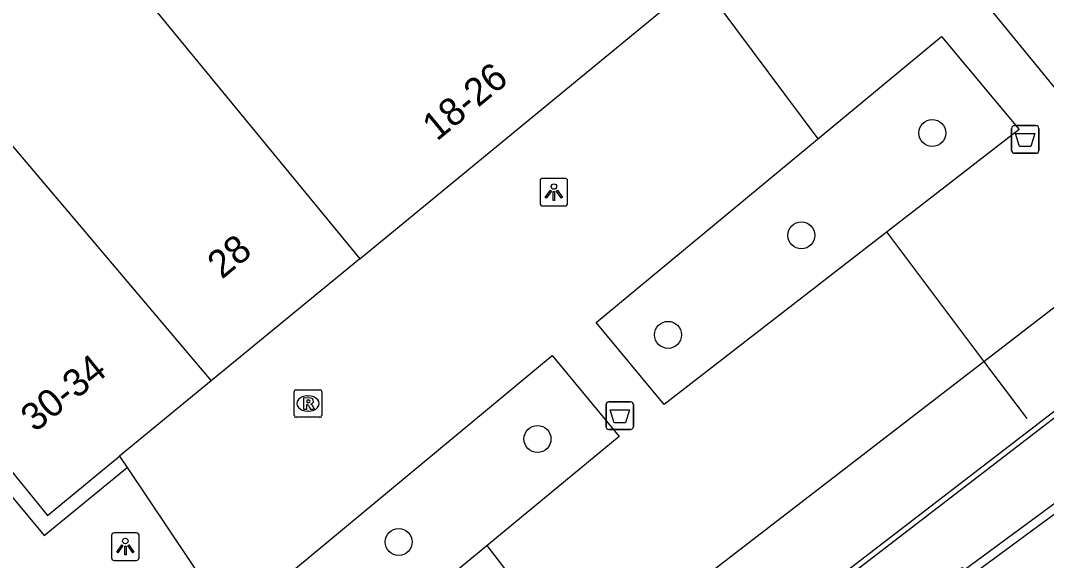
# Model space of a CAD drawing. Extents: x 161087 to 161922, y 382574 to 383873.
# Drawn here: x 161349.71 to 161386.87, y 383109.41 to 383128.96 of the extents above; entities that cross this region are included whole.
import ezdxf

# ---------------------------------------------------------------- set-up
doc = ezdxf.new("R2010")
doc.units = 0
for name, color, linetype in [('IMGEO_Afvalbak', 7, 'Continuous'), ('IMGEO_Boom', 7, 'Continuous'), ('IMGEO_Lichtpunt', 7, 'Continuous'), ('IMGEO_Lijnafwatering', 7, 'Continuous'), ('IMGEO_Muur', 7, 'Continuous'), ('IMGEO_Pand', 7, 'Continuous'), ('IMGEO_Pand_nummerreeks', 7, 'Continuous'), ('IMGEO_Rioolput', 7, 'Continuous'), ('IMGEO_Voetgangersgebied_open', 7, 'Continuous')]:
    doc.layers.add(name, color=color, linetype=linetype)

msp = doc.modelspace()

# ---------------------------------------------------------------- linework, layer by layer
at = {"layer": 'IMGEO_Afvalbak'}
for p, q in [((161385.607, 383124.25), (161385.607, 383125.05)), ((161385.607, 383125.05), (161385.607, 383124.25)), ((161385.707, 383125.15), (161386.497, 383125.15)), ((161386.497, 383125.15), (161385.707, 383125.15)), ((161386.597, 383125.05), (161386.597, 383124.25)), ((161386.597, 383124.25), (161386.597, 383125.05)), ((161386.497, 383124.15), (161385.707, 383124.15)), ((161385.707, 383124.15), (161386.497, 383124.15)), ((161370.919, 383114.252), (161370.919, 383115.052)), ((161370.919, 383115.052), (161370.919, 383114.252)), ((161371.019, 383115.152), (161371.809, 383115.152)), ((161371.809, 383115.152), (161371.019, 383115.152)), ((161371.909, 383115.052), (161371.909, 383114.252)), ((161371.909, 383114.252), (161371.909, 383115.052)), ((161371.809, 383114.152), (161371.019, 383114.152)), ((161371.019, 383114.152), (161371.809, 383114.152))]:
    msp.add_line(p, q, dxfattribs=at)
for points in [[(161385.75, 383124.864), (161386.454, 383124.864), (161386.305, 383124.394), (161385.899, 383124.394), (161385.75, 383124.864)], [(161371.062, 383114.866), (161371.766, 383114.866), (161371.617, 383114.396), (161371.211, 383114.396), (161371.062, 383114.866)]]:
    msp.add_lwpolyline(points, dxfattribs=at)
for centre, start, end in [((161385.707, 383125.05), 90, 180), ((161385.707, 383125.05), 90, 180), ((161386.497, 383125.05), 0, 90), ((161386.497, 383125.05), 360, 90), ((161385.707, 383124.25), 180, 270), ((161385.707, 383124.25), 180, 270), ((161386.497, 383124.25), 270, 0), ((161386.497, 383124.25), 270, 0), ((161371.019, 383115.052), 90, 180), ((161371.019, 383115.052), 90, 180), ((161371.809, 383115.052), 0, 90), ((161371.809, 383115.052), 360, 90), ((161371.019, 383114.252), 180, 270), ((161371.019, 383114.252), 180, 270), ((161371.809, 383114.252), 270, 0), ((161371.809, 383114.252), 270, 0)]:
    msp.add_arc(centre, 0.1, start, end, dxfattribs=at)
at = {"layer": 'IMGEO_Boom'}
for centre in [(161382.735, 383124.885), (161377.996, 383121.178), (161373.166, 383117.575), (161368.435, 383113.807), (161363.406, 383110.079)]:
    msp.add_circle(centre, 0.489, dxfattribs=at)
at = {"layer": 'IMGEO_Lichtpunt'}
for p, q in [((161368.53, 383123.147), (161368.53, 383122.34)), ((161368.53, 383123.147), (161368.53, 383122.34)), ((161369.432, 383123.242), (161368.624, 383123.242)), ((161369.432, 383123.242), (161368.624, 383123.242)), ((161369.526, 383122.34), (161369.526, 383123.147)), ((161369.526, 383122.34), (161369.526, 383123.147)), ((161368.624, 383122.246), (161369.432, 383122.246)), ((161368.624, 383122.246), (161369.432, 383122.246)), ((161353.909, 383110.408), (161353.101, 383110.408)), ((161353.909, 383110.408), (161353.101, 383110.408)), ((161353.007, 383110.313), (161353.007, 383109.506)), ((161353.007, 383110.313), (161353.007, 383109.506)), ((161354.003, 383109.506), (161354.003, 383110.313)), ((161354.003, 383109.506), (161354.003, 383110.313)), ((161353.101, 383109.412), (161353.909, 383109.412)), ((161353.101, 383109.412), (161353.909, 383109.412))]:
    msp.add_line(p, q, dxfattribs=at)
for points in [[(161368.904, 383122.811), (161368.943, 383122.783), (161368.755, 383122.521), (161368.717, 383122.548), (161368.904, 383122.811)], [(161369.006, 383122.763), (161369.053, 383122.763), (161369.053, 383122.441), (161369.006, 383122.441), (161369.006, 383122.763)], [(161369.116, 383122.783), (161369.154, 383122.81), (161369.341, 383122.548), (161369.302, 383122.52), (161369.116, 383122.783)], [(161353.381, 383109.977), (161353.42, 383109.949), (161353.232, 383109.687), (161353.194, 383109.714), (161353.381, 383109.977)], [(161353.483, 383109.929), (161353.53, 383109.929), (161353.53, 383109.607), (161353.483, 383109.607), (161353.483, 383109.929)], [(161353.593, 383109.949), (161353.631, 383109.976), (161353.818, 383109.714), (161353.779, 383109.686), (161353.593, 383109.949)]]:
    msp.add_lwpolyline(points, dxfattribs=at)
for centre in [(161369.029, 383122.945), (161353.506, 383110.111)]:
    msp.add_circle(centre, 0.0994, dxfattribs=at)
for centre, start, end in [((161368.624, 383123.147), 90, 180), ((161368.624, 383123.147), 90, 180), ((161369.432, 383123.147), 0, 90), ((161369.432, 383123.147), 0, 90), ((161368.624, 383122.34), 180, 270), ((161368.624, 383122.34), 180, 270), ((161369.432, 383122.34), 270, 0), ((161369.432, 383122.34), 270, 360), ((161353.101, 383110.313), 90, 180), ((161353.101, 383110.313), 90, 180), ((161353.909, 383110.313), 0, 90), ((161353.909, 383110.313), 0, 90), ((161353.101, 383109.506), 180, 270), ((161353.101, 383109.506), 180, 270), ((161353.909, 383109.506), 270, 0), ((161353.909, 383109.506), 270, 360)]:
    msp.add_arc(centre, 0.0946, start, end, dxfattribs=at)
at = {"layer": 'IMGEO_Lijnafwatering'}
for points in [[(161378.599, 383124.675), (161375.014, 383129.473)], [(161386.413, 383114.242), (161400.925, 383125.4)], [(161386.169, 383114.545), (161384.609, 383116.624), (161381.095, 383121.307)], [(161371.911, 383103.092), (161386.413, 383114.242)], [(161371.832, 383103.147), (161370.078, 383105.431), (161366.613, 383109.945)]]:
    msp.add_lwpolyline(points, dxfattribs=at)
at = {"layer": 'IMGEO_Muur'}
for points in [[(161383.403, 383108.826), (161383.816, 383109.153), (161383.887, 383109.068), (161387.88, 383112.004), (161395.4, 383117.308), (161399.385, 383120.025), (161404.347, 383123.179), (161413.367, 383127.97), (161413.315, 383128.067), (161413.877, 383128.367)], [(161415.27, 383125.521), (161413.802, 383127.485), (161413.669, 383127.408), (161413.514, 383127.686), (161410.831, 383126.299), (161404.509, 383122.902), (161399.561, 383119.758), (161395.582, 383117.045), (161388.067, 383111.744), (161384.079, 383108.819), (161384.146, 383108.732), (161384.022, 383108.636)]]:
    msp.add_lwpolyline(points, dxfattribs=at)
at = {"layer": 'IMGEO_Pand'}
for points in [[(161351.5, 383133.112), (161361.997, 383120.329)], [(161361.997, 383120.329), (161372.85, 383129.246)], [(161345.91, 383128.541), (161356.619, 383115.911)], [(161361.997, 383120.329), (161356.619, 383115.911)], [(161356.619, 383115.911), (161353.296, 383113.18)], [(161347.363, 383115.097), (161348.48, 383113.738), (161349.746, 383112.193), (161350.691, 383111.04), (161353.296, 383113.18)]]:
    msp.add_lwpolyline(points, dxfattribs=at)
at = {"layer": 'IMGEO_Rioolput'}
for p, q in [((161359.697, 383115.59), (161360.549, 383115.59)), ((161359.622, 383114.664), (161359.622, 383115.516)), ((161360.11, 383115.37), (161360.135, 383115.37)), ((161360.623, 383115.516), (161360.623, 383114.664)), ((161360.549, 383114.59), (161359.697, 383114.59)), ((161360.133, 383114.81), (161360.108, 383114.81))]:
    msp.add_line(p, q, dxfattribs=at)
for points in [[(161359.697, 383115.59), (161360.549, 383115.59)], [(161359.622, 383114.664), (161359.622, 383115.516)], [(161360.211, 383115.288), (161359.959, 383115.29), (161359.959, 383114.89)], [(161360.623, 383115.516), (161360.623, 383114.664)], [(161359.959, 383114.89), (161360.083, 383114.89), (161360.083, 383115.052), (161360.094, 383115.052)], [(161360.137, 383115.209), (161360.083, 383115.209), (161360.083, 383115.128)], [(161360.083, 383115.128), (161360.135, 383115.128)], [(161360.141, 383115.023), (161360.212, 383114.89), (161360.352, 383114.89), (161360.287, 383115.016)], [(161360.549, 383114.59), (161359.697, 383114.59)]]:
    msp.add_lwpolyline(points, dxfattribs=at)
for centre, radius, start, end in [((161359.699, 383115.514), 0.0765, 91.552, 178.448), ((161359.699, 383115.514), 0.0765, 91.552, 178.448), ((161360.547, 383115.514), 0.0765, 1.552, 88.448), ((161360.547, 383115.514), 0.0765, 1.552, 88.448), ((161360.21, 383115.178), 0.109, 350.3612, 89.416), ((161360.093, 383114.999), 0.0533, 26.0293, 88.6989), ((161360.119, 383115.317), 0.19, 274.7715, 282.9687), ((161360.143, 383115.113), 0.0964, 77.0061, 93.1865), ((161360.157, 383115.17), 0.0378, 276.6634, 79.6772), ((161360.208, 383115.178), 0.112, 277.5842, 350.9817), ((161360.192, 383114.963), 0.108, 29.5134, 73.7905), ((161359.699, 383114.666), 0.0765, 181.552, 268.448), ((161359.699, 383114.666), 0.0765, 181.552, 268.448), ((161360.547, 383114.666), 0.0765, 271.552, 358.448), ((161360.547, 383114.666), 0.0765, 271.552, 358.448)]:
    msp.add_arc(centre, radius, start, end, dxfattribs=at)
for centre, major_axis, ratio, start_param, end_param in [((161360.109, 383115.09), (-0.387, 0.002), 0.722429, 4.712389, 7.853982), ((161360.134, 383115.09), (-0.39, 0.002), 0.717154, 1.570796, 4.712389)]:
    msp.add_ellipse(centre, major_axis=major_axis, ratio=ratio, start_param=start_param, end_param=end_param, dxfattribs=at)
at = {"layer": 'IMGEO_Voetgangersgebied_open'}
for points in [[(161362.866, 383099.876), (161421.439, 383144.995)], [(161397.058, 383139.799), (161400.206, 383136.021), (161387.42, 383126.235), (161384.635, 383129.62), (161397.058, 383139.799)], [(161410.626, 383132.608), (161409.678, 383131.89), (161364.77, 383097.35)], [(161385.878, 383125.009), (161373.018, 383115.058), (161370.565, 383118.026), (161383.075, 383128.38), (161385.878, 383125.009)], [(161357.325, 383107.176), (161368.972, 383116.831), (161371.397, 383113.893), (161359.598, 383104.154)], [(161346.896, 383114.722), (161350.565, 383110.309), (161353.567, 383112.777)], [(161353.296, 383113.18), (161353.567, 383112.777)], [(161353.567, 383112.777), (161357.325, 383107.176)]]:
    msp.add_lwpolyline(points, dxfattribs=at)

# ---------------------------------------------------------------- texts
at = {"layer": 'IMGEO_Pand_nummerreeks'}
for s, rotation, p in [('18-26', 39.408, (161364.79, 383124.564)), ('28', 39.3957, (161357.003, 383119.569)), ('30-34', 38.7488, (161350.232, 383114.025))]:
    msp.add_text(s, height=1, rotation=rotation, dxfattribs=at).set_placement(p)

doc.saveas('drawing.dxf')
